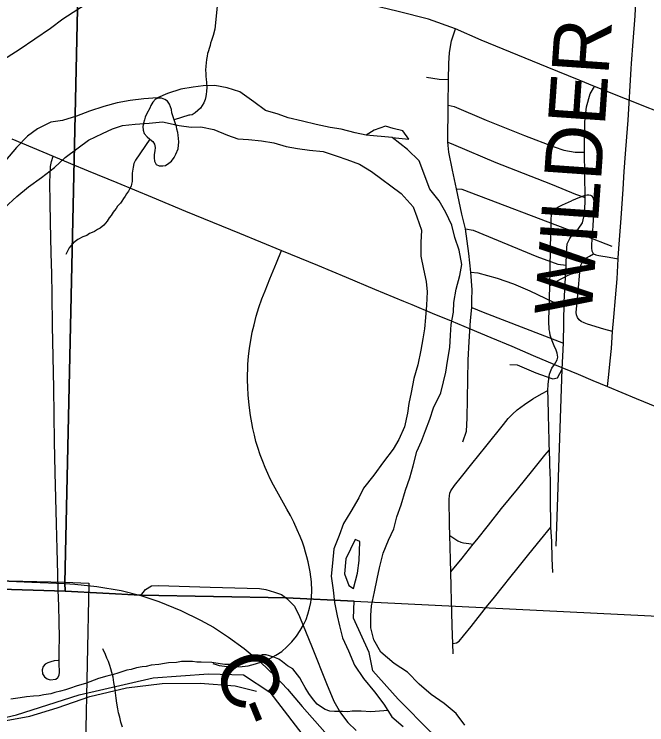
# Model space of a CAD drawing. Extents: x -6.1 to 38, y -7.7 to 22.
# Drawn here: x 3.241 to 3.87, y 19.926 to 20.633 of the extents above; entities that cross this region are included whole.
import ezdxf

# ---------------------------------------------------------------- set-up
doc = ezdxf.new("R2010")
doc.units = 0
for name, color, linetype in [('GM_X_Corporation', 7, 'Continuous'), ('GM_X_County_Road', 7, 'Continuous'), ('GM_X_County_Road_Text', 7, 'Continuous'), ('GM_X_Major_River', 7, 'Continuous'), ('GM_X_Minor_Lake', 7, 'Continuous'), ('GM_X_Minor_River', 7, 'Continuous'), ('GM_X_Rail_Line', 7, 'Continuous'), ('GM_X_Township_Road', 7, 'Continuous'), ('GM_X_Township_Road_Text', 7, 'Continuous'), ('GM_X_US_Route', 7, 'Continuous')]:
    doc.layers.add(name, color=color, linetype=linetype)

msp = doc.modelspace()

# ---------------------------------------------------------------- linework, layer by layer
at = {"layer": 'GM_X_Corporation'}
for points in [[(3.3101, 20.9), (2.1, 20.9), (2.1, 20.09414), (2.34776, 20.08659), (2.61918, 20.0796), (3.29133, 20.05869), (3.29106, 20.06691), (3.30388, 20.63802)], [(2.34542, 20.09827), (2.41961, 20.09248), (2.47052, 20.0902), (2.61883, 20.08595), (2.79073, 20.08068), (2.90281, 20.07752), (3.06866, 20.07303), (3.29109, 20.06779), (3.31497, 20.0668), (3.29694, 19.18347), (3.29403, 19.05339), (2.3594, 19.07674)]]:
    msp.add_lwpolyline(points, close=True, dxfattribs=at)
for points in [[(8.04941, 20.9), (3.3101, 20.9), (3.30388, 20.63802), (3.29106, 20.06691), (3.29133, 20.05869), (3.36656, 20.05475), (3.51164, 20.05197), (3.57893, 20.04876), (4.40517, 20.00794)], [(4.32021, 19.88191), (4.2291, 19.86308), (4.15368, 19.82382), (4.11127, 19.79868), (4.06254, 19.73585), (4.02327, 19.71072), (3.98871, 19.69973), (3.94944, 19.70602), (3.91017, 19.71546), (3.82222, 19.76103), (3.77511, 19.81289), (3.74056, 19.84589), (3.7123, 19.87731), (3.68403, 19.90089), (3.65576, 19.91817), (3.62279, 19.95117), (3.59767, 19.97946), (3.59394, 19.99773), (3.57833, 20.03194), (3.57893, 20.04876), (3.51164, 20.05197), (3.36656, 20.05475), (3.29133, 20.05869), (2.61918, 20.0796)], [(4.32021, 19.88191), (4.2291, 19.86308), (4.15368, 19.82382), (4.11127, 19.79868), (4.06254, 19.73585), (4.02327, 19.71072), (3.98871, 19.69973), (3.94944, 19.70602), (3.91017, 19.71546), (3.82222, 19.76103), (3.77511, 19.81289), (3.74056, 19.84589), (3.7123, 19.87731), (3.68403, 19.90089), (3.65576, 19.91817), (3.62279, 19.95117), (3.59767, 19.97946), (3.59394, 19.99773), (3.57833, 20.03194), (3.57893, 20.04876), (4.40517, 20.00794)]]:
    msp.add_lwpolyline(points, dxfattribs=at)
at = {"layer": 'GM_X_County_Road'}
msp.add_line((3.84888, 20.54874), (3.81814, 20.56102), dxfattribs=at)
for points in [[(3.81814, 20.56102), (3.80273, 20.5674), (3.77098, 20.58017), (3.70529, 20.60713), (3.67972, 20.61831), (3.65308, 20.62806), (3.62284, 20.63557), (3.58683, 20.64406), (3.51569, 20.66388), (3.47133, 20.67632), (3.45033, 20.68331), (3.43708, 20.68882), (3.42733, 20.69532), (3.41983, 20.70357)], [(3.34234, 20.66057), (3.33982, 20.65907), (3.31907, 20.64706), (3.30409, 20.63748), (3.28932, 20.62781), (3.27682, 20.61857), (3.24582, 20.59756), (3.21057, 20.57506)], [(3.89917, 20.52865), (3.84888, 20.54874)], [(3.36677, 20.05421), (3.37136, 20.06033), (3.37748, 20.06383), (3.38426, 20.06426), (3.43584, 20.06273), (3.4848, 20.0612), (3.49106, 20.06017), (3.49968, 20.05784), (3.50665, 20.05552), (3.51185, 20.05143), (3.51955, 20.04372), (3.52457, 20.03345), (3.53726, 20.00263), (3.55146, 19.96678), (3.55889, 19.94908), (3.56545, 19.93771), (3.57266, 19.92809), (3.58102, 19.92004)]]:
    msp.add_lwpolyline(points, dxfattribs=at)
at = {"layer": 'GM_X_Major_River'}
msp.add_line((3.61686, 20.5103), (3.59078, 20.51247), dxfattribs=at)
for points in [[(3.58004, 20.51487), (3.56604, 20.51864), (3.55507, 20.52013), (3.54108, 20.52314), (3.52746, 20.52653), (3.51347, 20.52991), (3.50325, 20.53331), (3.49077, 20.53707), (3.47903, 20.54577), (3.4654, 20.5556), (3.45254, 20.55975), (3.44044, 20.562), (3.42872, 20.5616), (3.41889, 20.56044), (3.40642, 20.55814), (3.39319, 20.55395), (3.38337, 20.54976), (3.36976, 20.5486), (3.35615, 20.54706), (3.3433, 20.54476), (3.33007, 20.54094), (3.31572, 20.53636), (3.30287, 20.53141), (3.28889, 20.52722), (3.27717, 20.5253), (3.26395, 20.51883), (3.25413, 20.51161), (3.24319, 20.50021), (3.23225, 20.4873)], [(3.23119, 20.44029), (3.24327, 20.45131), (3.25497, 20.46118), (3.26781, 20.47031), (3.28103, 20.48019), (3.2916, 20.49045), (3.30444, 20.49995), (3.31463, 20.50755), (3.32861, 20.51402), (3.33843, 20.51897), (3.34863, 20.52202), (3.36111, 20.52356), (3.3751, 20.52435), (3.38833, 20.52589), (3.40497, 20.52213), (3.41669, 20.52063), (3.42652, 20.52065), (3.43938, 20.51802), (3.453, 20.51236), (3.46322, 20.50896), (3.4738, 20.50823), (3.48666, 20.50674), (3.49914, 20.50486), (3.51125, 20.50109), (3.52259, 20.49922), (3.53469, 20.49773), (3.54831, 20.49623), (3.56193, 20.49171), (3.57176, 20.48832), (3.58425, 20.48379), (3.59636, 20.47623), (3.62589, 20.4543), (3.63763, 20.44105), (3.64143, 20.4312), (3.64599, 20.41794), (3.64525, 20.4058), (3.64528, 20.39216), (3.64795, 20.37927), (3.65061, 20.36676), (3.65177, 20.35653), (3.65103, 20.34326), (3.64992, 20.33113), (3.64881, 20.31975), (3.64731, 20.30989), (3.64544, 20.29851), (3.64244, 20.2841), (3.63831, 20.27044), (3.63568, 20.25641), (3.63343, 20.24541), (3.63194, 20.23593), (3.62894, 20.22228), (3.62329, 20.20976), (3.61764, 20.19989), (3.60821, 20.18736), (3.5984, 20.17407), (3.58822, 20.16117), (3.58369, 20.15168), (3.57578, 20.13802), (3.56824, 20.12587), (3.5641, 20.11411), (3.55883, 20.10083), (3.55735, 20.08642), (3.55623, 20.07353), (3.55815, 20.05951), (3.55931, 20.04738), (3.56198, 20.03412), (3.56426, 20.02426), (3.56731, 20.01214), (3.57338, 19.99926), (3.57946, 19.98487), (3.58818, 19.97161), (3.59917, 19.95837), (3.60864, 19.94625), (3.61661, 19.93376), (3.62759, 19.92392)], [(3.61686, 20.5103), (3.63336, 20.50853), (3.62741, 20.51679), (3.61796, 20.51903), (3.61027, 20.52137), (3.59893, 20.51756), (3.59078, 20.51247)], [(3.59078, 20.51247), (3.58004, 20.51487)], [(3.68921, 19.92518), (3.6805, 19.93691), (3.66838, 19.94675), (3.65551, 19.95582), (3.64377, 19.96603), (3.63203, 19.97814), (3.61878, 19.98684), (3.60552, 19.9978), (3.59869, 20.0103), (3.59565, 20.02205), (3.59563, 20.03456), (3.59636, 20.04404), (3.59936, 20.05807), (3.60199, 20.07096), (3.60424, 20.08196), (3.60799, 20.09638), (3.61326, 20.10928), (3.61854, 20.12066), (3.62154, 20.1328), (3.62568, 20.14456), (3.63018, 20.15935), (3.63432, 20.17149), (3.6377, 20.18325), (3.64146, 20.19766), (3.64598, 20.2079), (3.65012, 20.21853), (3.65425, 20.22991), (3.65802, 20.24129), (3.66518, 20.25609), (3.6678, 20.26709), (3.67005, 20.27657), (3.67193, 20.28757), (3.67417, 20.30122), (3.6749, 20.31335), (3.67564, 20.32397), (3.67789, 20.33649), (3.67825, 20.34596), (3.6805, 20.35924), (3.68425, 20.37289), (3.68612, 20.38389), (3.68345, 20.39792), (3.67927, 20.4108), (3.67623, 20.42292), (3.67015, 20.43542), (3.66371, 20.44716), (3.65423, 20.4589), (3.6436, 20.48694), (3.63203, 20.49823), (3.61686, 20.5103)], [(3.58467, 20.10794), (3.58012, 20.11019), (3.57076, 20.09082), (3.56932, 20.07603), (3.57353, 20.06429), (3.57846, 20.06128)], [(3.57846, 20.06128), (3.58232, 20.07661), (3.58381, 20.08913), (3.58467, 20.10794)]]:
    msp.add_lwpolyline(points, dxfattribs=at)
at = {"layer": 'GM_X_Minor_Lake'}
for points in [[(3.39993, 20.5277), (3.3976, 20.5349), (3.3972, 20.53793), (3.39643, 20.54058), (3.39527, 20.54323), (3.39336, 20.54625), (3.39069, 20.54813), (3.38728, 20.54924), (3.38387, 20.54922), (3.38122, 20.54844), (3.37859, 20.54539), (3.37672, 20.54196), (3.3756, 20.5393), (3.37261, 20.53396), (3.37111, 20.53054), (3.37037, 20.52788), (3.36926, 20.52445), (3.3689, 20.52104), (3.36893, 20.51762), (3.37009, 20.51421), (3.37314, 20.51082), (3.37581, 20.50856), (3.37886, 20.50631), (3.38039, 20.50366), (3.38117, 20.50025), (3.38081, 20.49683), (3.38008, 20.49341), (3.3801, 20.49), (3.3805, 20.48658), (3.38204, 20.48318)], [(3.38204, 20.48318), (3.38508, 20.48206), (3.38849, 20.48208), (3.39114, 20.48248), (3.39454, 20.48478), (3.39718, 20.4867), (3.3998, 20.49013), (3.40168, 20.49356), (3.40391, 20.49889), (3.40462, 20.50572), (3.40382, 20.51255), (3.40342, 20.5152), (3.40264, 20.51861), (3.40224, 20.52126), (3.40108, 20.52467), (3.39993, 20.5277)]]:
    msp.add_lwpolyline(points, dxfattribs=at)
at = {"layer": 'GM_X_Minor_River'}
for points in [[(3.44379, 20.65133), (3.44043, 20.6181), (3.43861, 20.61162), (3.43714, 20.60666), (3.43603, 20.60399), (3.43568, 20.6017), (3.43494, 20.59979), (3.43385, 20.5956), (3.43311, 20.59369), (3.43276, 20.59103), (3.43204, 20.58798), (3.4317, 20.58455), (3.43136, 20.58113), (3.43102, 20.57732), (3.43144, 20.5739), (3.43148, 20.57086), (3.43189, 20.56821), (3.43193, 20.56479), (3.43236, 20.56023), (3.43203, 20.55604), (3.43168, 20.55338), (3.43132, 20.55109), (3.4306, 20.54804), (3.4295, 20.54461), (3.42763, 20.54193), (3.42614, 20.53925), (3.42087, 20.53464), (3.41785, 20.53271), (3.41558, 20.53231), (3.41444, 20.53229), (3.39993, 20.5277)], [(3.37581, 20.50856), (3.36135, 20.48766), (3.35987, 20.48423), (3.35915, 20.4808), (3.35808, 20.4747), (3.35811, 20.47204), (3.35815, 20.46824), (3.35818, 20.46634), (3.35745, 20.46367), (3.35709, 20.46177), (3.3556, 20.45871), (3.35448, 20.4568), (3.35262, 20.45412), (3.35112, 20.45182), (3.34963, 20.44952), (3.34776, 20.44685), (3.34664, 20.44493), (3.34363, 20.44186), (3.34214, 20.43957), (3.34064, 20.43765), (3.33914, 20.43573), (3.33728, 20.43268), (3.3354, 20.43037), (3.33316, 20.42693), (3.32979, 20.42309), (3.3264, 20.42002), (3.32376, 20.41847), (3.32074, 20.41654), (3.31847, 20.41576), (3.31582, 20.41459), (3.31318, 20.41266), (3.30901, 20.41148), (3.3041, 20.40877), (3.30146, 20.40684), (3.29958, 20.40492), (3.29695, 20.40224), (3.29545, 20.40032), (3.29397, 20.39764), (3.29286, 20.39497), (3.29211, 20.39382)], [(3.34852, 19.92331), (3.34694, 19.92824), (3.34574, 19.93317), (3.34455, 19.93772), (3.34374, 19.94151), (3.34292, 19.94721), (3.3421, 19.95215), (3.34166, 19.95746), (3.34083, 19.96278), (3.34002, 19.96771), (3.33919, 19.97303), (3.338, 19.97758), (3.33682, 19.98137), (3.33602, 19.98478), (3.33445, 19.98857), (3.33289, 19.99198), (3.33171, 19.99576), (3.32937, 20.00069), (3.32902, 20.0013)], [(3.61268, 19.93992), (3.59564, 19.93853), (3.58581, 19.93925), (3.57712, 19.93921), (3.57259, 19.93844), (3.5673, 19.93879), (3.55937, 19.93876), (3.55483, 19.93912), (3.55029, 19.941), (3.5465, 19.94326), (3.54233, 19.94627), (3.53854, 19.95043), (3.53397, 19.95685), (3.53017, 19.9629), (3.52712, 19.9682), (3.52483, 19.97236), (3.51799, 19.98143), (3.51269, 19.98444), (3.50776, 19.98821), (3.50397, 19.99085), (3.49905, 19.9931), (3.49148, 19.99534), (3.48732, 19.99533), (3.47941, 19.9915), (3.473, 19.98844), (3.46432, 19.98651), (3.45866, 19.98573), (3.45034, 19.9857), (3.44581, 19.98644), (3.43749, 19.98754), (3.42691, 19.98788), (3.42237, 19.98786), (3.41822, 19.9886), (3.40726, 19.98855), (3.40235, 19.98777), (3.39442, 19.98736), (3.39027, 19.98659), (3.3846, 19.98581), (3.37705, 19.98502), (3.37214, 19.98386), (3.36799, 19.98346), (3.36233, 19.9823), (3.35704, 19.98077), (3.35289, 19.97999), (3.34874, 19.97884), (3.34384, 19.97692), (3.33969, 19.97577), (3.33289, 19.97422), (3.3246, 19.97191), (3.31177, 19.96693), (3.30347, 19.96462), (3.29593, 19.96194), (3.29178, 19.96041), (3.28687, 19.95925), (3.28121, 19.95771), (3.27706, 19.95656), (3.27026, 19.95539), (3.26574, 19.95461), (3.26007, 19.95421), (3.25289, 19.95342), (3.24685, 19.95264), (3.23741, 19.95109)], [(3.2292, 19.92944), (3.25638, 19.9341), (3.28355, 19.94256), (3.31599, 19.95368), (3.3526, 19.96255), (3.38809, 19.96687), (3.42587, 19.96702), (3.46064, 19.96451), (3.48182, 19.95929)]]:
    msp.add_lwpolyline(points, dxfattribs=at)
at = {"layer": 'GM_X_Rail_Line'}
msp.add_lwpolyline([(2.1, 20.22672), (2.72238, 19.85623), (2.78818, 19.82405), (2.83715, 19.81025), (2.88459, 19.81024), (2.93803, 19.82546), (2.99132, 19.87524), (3.04538, 19.90505), (3.0964, 19.92627), (3.15298, 19.92829), (3.20022, 19.92551), (3.24316, 19.93561), (3.30555, 19.95557), (3.37905, 19.97249), (3.43412, 19.97653), (3.46898, 19.97552), (3.495, 19.95808), (3.54553, 19.89238), (3.61618, 19.81161), (3.7762, 19.63742), (3.82168, 19.57425), (3.97265, 19.2587), (4.0109, 19.20357)], dxfattribs=at)
at = {"layer": 'GM_X_Township_Road'}
for points in [[(3.85467, 20.57865), (3.85504, 20.58369), (3.85664, 20.60589), (3.85849, 20.63141), (3.85985, 20.65977), (3.86074, 20.68629), (3.86157, 20.71082), (3.86193, 20.7274), (3.86229, 20.74399), (3.86273, 20.76446), (3.86318, 20.78492), (3.8633, 20.80287), (3.86342, 20.82081), (3.86354, 20.83067), (3.86318, 20.83844), (3.86206, 20.84584), (3.86009, 20.85262), (3.8575, 20.86014), (3.85455, 20.86742), (3.85023, 20.87555), (3.84505, 20.88418), (3.8374, 20.89688), (3.83556, 20.9)], [(3.68711, 20.20717), (3.69071, 20.21795), (3.6915, 20.23073), (3.69233, 20.28845), (3.6935, 20.30701), (3.6947, 20.32818), (3.6959, 20.34096), (3.6959, 20.34854), (3.6963, 20.35853), (3.6951, 20.3761), (3.6931, 20.39467), (3.68971, 20.41943), (3.68612, 20.43401), (3.68072, 20.45917), (3.67693, 20.47774), (3.67314, 20.49551), (3.67214, 20.5057), (3.67253, 20.54244), (3.67294, 20.5676), (3.67314, 20.58397), (3.67373, 20.59495), (3.67593, 20.60653), (3.67972, 20.61831)], [(3.84179, 20.39047), (3.84271, 20.40417), (3.84468, 20.42993), (3.84665, 20.45891), (3.84777, 20.47648), (3.84887, 20.49405), (3.85017, 20.51076), (3.85146, 20.52746), (3.85245, 20.54448), (3.85343, 20.5615), (3.85467, 20.57865)], [(3.67294, 20.5676), (3.66355, 20.56779), (3.65097, 20.56999)], [(3.78011, 20.10349), (3.78579, 20.27968), (3.78715, 20.30561), (3.78795, 20.34634), (3.78975, 20.38329), (3.79015, 20.39527), (3.79095, 20.40446), (3.79355, 20.40964), (3.79783, 20.4164), (3.80173, 20.41903), (3.80612, 20.42542), (3.80832, 20.43541), (3.80872, 20.45038), (3.80812, 20.49551), (3.80852, 20.52566), (3.81012, 20.54084), (3.81391, 20.55362), (3.81814, 20.56102)], [(3.67253, 20.54244), (3.67852, 20.54104), (3.71047, 20.52746), (3.74842, 20.51208), (3.77797, 20.5009), (3.78775, 20.4977), (3.79873, 20.49551), (3.80812, 20.49551)], [(3.67214, 20.5057), (3.67773, 20.5031), (3.71986, 20.48533), (3.73963, 20.47754), (3.77597, 20.46336), (3.79913, 20.45377), (3.80872, 20.45038)], [(3.28464, 20.0597), (3.28422, 20.07543), (3.28356, 20.10055), (3.2829, 20.12566), (3.28223, 20.15117), (3.28156, 20.17668), (3.28101, 20.20774), (3.28054, 20.23421), (3.28007, 20.26069), (3.27952, 20.29175), (3.27897, 20.32281), (3.27842, 20.35387), (3.27806, 20.37443), (3.27769, 20.39498), (3.27704, 20.42604), (3.27663, 20.44565), (3.27622, 20.46526), (3.27674, 20.48122), (3.27781, 20.48619), (3.27942, 20.4917)], [(3.68072, 20.45917), (3.68611, 20.45871), (3.79783, 20.4164), (3.80352, 20.41584), (3.80972, 20.41204), (3.83528, 20.40206)], [(3.81698, 20.3945), (3.81583, 20.39718), (3.81551, 20.40031), (3.81536, 20.40356), (3.81665, 20.42231), (3.81793, 20.44105), (3.81803, 20.44591), (3.81688, 20.45048), (3.81583, 20.45172), (3.81431, 20.45258), (3.8124, 20.45296), (3.81066, 20.45288), (3.80774, 20.4522), (3.80306, 20.45039), (3.79507, 20.44705)], [(3.7782, 20.28435), (3.77969, 20.28661), (3.78106, 20.28907), (3.78167, 20.29172), (3.7811, 20.29545), (3.78002, 20.29856), (3.77789, 20.30285), (3.77586, 20.30779), (3.77496, 20.31061), (3.77415, 20.31349), (3.77354, 20.31639), (3.77307, 20.31922), (3.77271, 20.32735), (3.77284, 20.33955), (3.77322, 20.35009), (3.77372, 20.36293), (3.77398, 20.37818), (3.77442, 20.40099), (3.77485, 20.4238), (3.77505, 20.42885), (3.77543, 20.43285), (3.77628, 20.43552), (3.77762, 20.4379), (3.77953, 20.43952), (3.78213, 20.44104), (3.78631, 20.44311), (3.79507, 20.44705)], [(3.68971, 20.41943), (3.69724, 20.41783), (3.76059, 20.39167), (3.78176, 20.38429), (3.78975, 20.38329)], [(3.43832, 19.98652), (3.44155, 19.98557), (3.44481, 19.98476), (3.45, 19.98393), (3.45559, 19.98355), (3.46095, 19.98348), (3.46753, 19.98373), (3.47345, 19.98449), (3.48068, 19.98624), (3.48824, 19.98876), (3.49511, 19.99168), (3.50111, 19.99489), (3.50687, 19.99877), (3.5121, 20.00335), (3.51705, 20.00837), (3.52158, 20.0139), (3.5254, 20.01953), (3.52848, 20.02507), (3.53108, 20.03039), (3.53302, 20.03566), (3.53465, 20.04161), (3.53579, 20.04738), (3.53667, 20.05274), (3.53699, 20.05888), (3.53663, 20.06796), (3.53597, 20.07296), (3.53517, 20.07795), (3.53422, 20.08292), (3.53314, 20.08786), (3.53196, 20.09277), (3.53063, 20.09764), (3.52916, 20.10248), (3.52756, 20.10728), (3.52517, 20.11305), (3.52242, 20.11969), (3.51881, 20.12747), (3.51567, 20.13385), (3.51209, 20.14033), (3.50358, 20.1553), (3.49876, 20.16417), (3.49558, 20.17031), (3.49306, 20.17589), (3.49043, 20.18192), (3.48802, 20.18773), (3.48561, 20.1943), (3.48309, 20.20176), (3.48123, 20.20767), (3.47969, 20.21392), (3.47816, 20.2206), (3.47706, 20.22619), (3.47586, 20.23364), (3.47476, 20.24098), (3.47411, 20.24722), (3.47345, 20.25402), (3.47312, 20.26136), (3.47301, 20.26892), (3.47334, 20.28448), (3.47399, 20.29236), (3.47476, 20.30058), (3.47608, 20.30825), (3.47761, 20.31636), (3.47936, 20.32381), (3.48144, 20.33235), (3.48418, 20.34112), (3.48725, 20.34955), (3.49032, 20.35766), (3.49514, 20.36939), (3.50171, 20.38538), (3.50675, 20.39788)], [(3.83617, 20.31699), (3.82729, 20.31958), (3.81107, 20.32436), (3.80774, 20.3256), (3.80487, 20.32703), (3.80278, 20.32884), (3.80106, 20.33113), (3.8003, 20.3338), (3.80001, 20.33608), (3.80183, 20.35695), (3.80347, 20.37628), (3.80364, 20.37916), (3.80402, 20.38164), (3.80487, 20.38393), (3.80621, 20.38631), (3.80783, 20.38832), (3.81012, 20.39032), (3.81298, 20.39222), (3.81698, 20.3945), (3.81946, 20.39355), (3.82241, 20.3927), (3.83263, 20.391), (3.84172, 20.38949)], [(3.831, 20.26236), (3.83235, 20.2742), (3.83371, 20.28798), (3.83494, 20.30034), (3.83617, 20.31699), (3.8374, 20.33154), (3.83894, 20.35052), (3.84049, 20.36951), (3.84172, 20.38949), (3.84179, 20.39047)], [(3.6951, 20.3761), (3.70209, 20.3755), (3.72126, 20.37011), (3.73763, 20.36452), (3.7536, 20.35773), (3.77658, 20.34677), (3.78795, 20.34634)], [(3.78754, 20.37098), (3.79129, 20.3728), (3.79437, 20.37402), (3.7975, 20.37502), (3.80347, 20.37628)], [(3.77372, 20.36293), (3.77881, 20.36623), (3.78351, 20.36903), (3.78754, 20.37098)], [(3.6959, 20.34096), (3.70738, 20.33651), (3.78715, 20.30561)], [(3.73394, 20.28411), (3.74123, 20.28385), (3.7596, 20.27606), (3.76998, 20.27227), (3.77677, 20.27007), (3.78136, 20.27107), (3.78579, 20.27968)], [(3.7765, 20.07726), (3.77594, 20.09134), (3.77562, 20.10826), (3.77477, 20.12234), (3.77446, 20.15174), (3.77418, 20.17135), (3.77408, 20.17402), (3.77357, 20.18715), (3.77325, 20.1995), (3.77311, 20.20419), (3.77297, 20.20876), (3.77222, 20.23377), (3.77204, 20.2501), (3.77182, 20.2585), (3.77215, 20.26433), (3.77273, 20.27004), (3.77348, 20.27464), (3.77418, 20.27739), (3.77559, 20.28057), (3.7782, 20.28435)], [(3.67758, 19.99624), (3.67706, 20.00658), (3.67673, 20.01502), (3.67645, 20.02439), (3.67618, 20.0373), (3.67599, 20.04895), (3.67552, 20.063), (3.67516, 20.07781), (3.67483, 20.08957), (3.67465, 20.10294), (3.67427, 20.11408), (3.67389, 20.12515), (3.67353, 20.15033), (3.67368, 20.1536), (3.6742, 20.15616), (3.67514, 20.15861), (3.67885, 20.16393), (3.68577, 20.17241), (3.69591, 20.18528), (3.70999, 20.20279), (3.72758, 20.22468), (3.73237, 20.23048), (3.73668, 20.23497), (3.74128, 20.23904), (3.7483, 20.24439), (3.75667, 20.25021), (3.76521, 20.25513), (3.77182, 20.2585)], [(3.67516, 20.07781), (3.68653, 20.09163), (3.69753, 20.10541), (3.70109, 20.10987), (3.71266, 20.12438), (3.72569, 20.1409), (3.74134, 20.16004), (3.7567, 20.17916), (3.7687, 20.19417), (3.77325, 20.1995)], [(3.67706, 20.00658), (3.68071, 20.00722), (3.68351, 20.00902), (3.68778, 20.01422), (3.69531, 20.02358), (3.71067, 20.04301), (3.71854, 20.05269), (3.72764, 20.06406), (3.734, 20.07193), (3.74201, 20.08217), (3.75291, 20.09566), (3.76439, 20.10984), (3.77477, 20.12234)], [(3.67427, 20.11408), (3.67627, 20.11271), (3.68218, 20.10866), (3.68502, 20.10735), (3.68776, 20.10663), (3.69316, 20.10595), (3.69753, 20.10541)], [(3.28454, 19.98982), (3.28056, 19.98922), (3.27713, 19.98841), (3.2743, 19.98751), (3.27174, 19.98598), (3.26969, 19.98357), (3.26861, 19.98031), (3.26908, 19.97646), (3.27089, 19.97345), (3.27366, 19.97128), (3.27656, 19.97031), (3.2821, 19.97103), (3.28403, 19.9726), (3.28549, 19.9752), (3.28596, 19.97802), (3.28548, 19.98658), (3.28554, 19.99937), (3.28568, 20.01242), (3.28537, 20.02819), (3.28506, 20.04397), (3.28464, 20.0597)]]:
    msp.add_lwpolyline(points, dxfattribs=at)
at = {"layer": 'GM_X_US_Route'}
for points in [[(3.23826, 20.509), (3.25884, 20.50035), (3.27942, 20.4917)], [(3.27942, 20.4917), (3.29681, 20.48443), (3.3142, 20.47716), (3.34292, 20.46531), (3.36054, 20.45804), (3.37817, 20.45076), (3.39473, 20.44383), (3.41127, 20.43691), (3.43804, 20.42598), (3.4648, 20.41505), (3.48577, 20.40647), (3.50675, 20.39788), (3.5246, 20.39045), (3.54244, 20.38303), (3.5709, 20.37117), (3.59935, 20.35931), (3.62803, 20.34736), (3.63635, 20.34389)], [(3.63635, 20.34389), (3.6567, 20.33541), (3.67549, 20.32758), (3.69427, 20.31975), (3.71507, 20.3111), (3.73588, 20.30244), (3.75705, 20.29339), (3.7782, 20.28435), (3.80192, 20.27453), (3.81646, 20.26845), (3.831, 20.26236), (3.85968, 20.25041), (3.87993, 20.24198)], [(2.61949, 20.08634), (2.69664, 20.08503), (2.80134, 20.08219), (2.87761, 20.07978), (2.9657, 20.07716), (3.11456, 20.07228), (3.21224, 20.06951), (3.25826, 20.06768)], [(3.25826, 20.06768), (3.29127, 20.06637), (3.30098, 20.0658), (3.32284, 20.06339), (3.3471, 20.05923), (3.36677, 20.05421)], [(3.36677, 20.05421), (3.38469, 20.04853), (3.40655, 20.03934), (3.42622, 20.02995), (3.4389, 20.02274), (3.45398, 20.0129), (3.46971, 20.00175), (3.48569, 19.98813), (3.50053, 19.974), (3.51277, 19.9611), (3.52742, 19.94405), (3.54971, 19.91826)]]:
    msp.add_lwpolyline(points, dxfattribs=at)

# ---------------------------------------------------------------- texts
at = {"layer": 'GM_X_County_Road_Text'}
for s, rotation, p in [('C', 291.9942, (3.43824, 19.98565)), ('-', 292.2851, (3.45583, 19.94209))]:
    msp.add_text(s, height=0.05682, rotation=rotation, dxfattribs=at).set_placement(p)
at = {"layer": 'GM_X_Township_Road_Text'}
msp.add_text('WILDER', height=0.056818, rotation=85.99992, dxfattribs=at).set_placement((3.81507, 20.33135))

doc.saveas('drawing.dxf')
